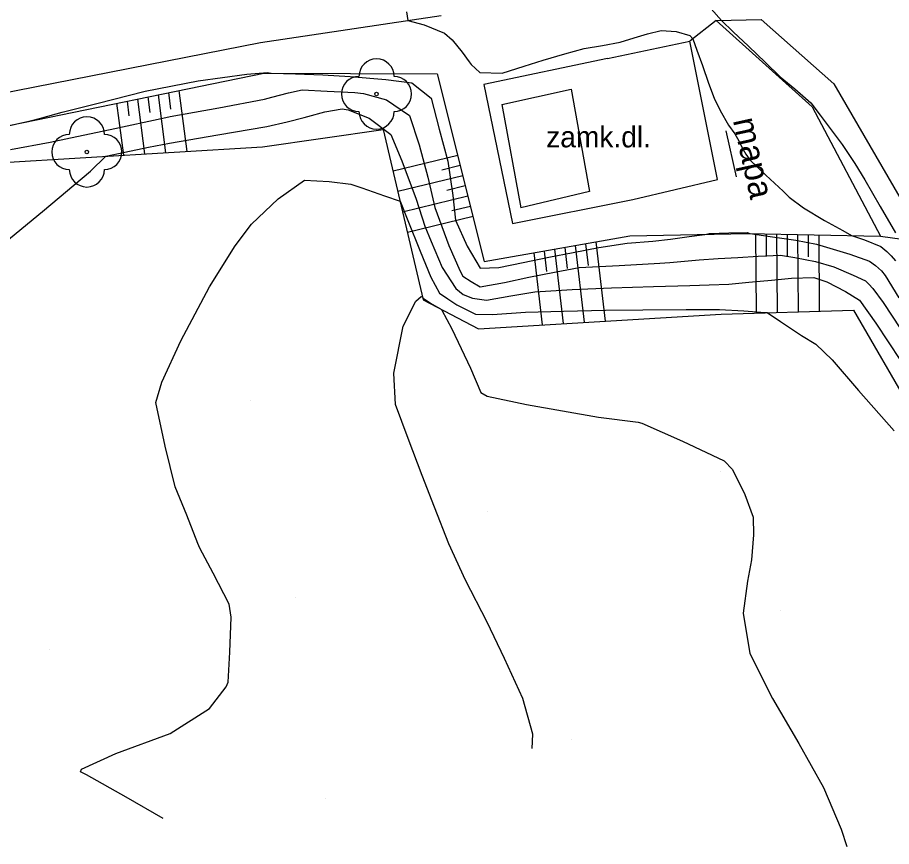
# Model space of a CAD drawing. Extents: x -448957 to -448612, y -1107690 to -1107245.
# Drawn here: x -448777.15 to -448752.23, y -1107406.9 to -1107383.27 of the extents above; entities that cross this region are included whole.
import ezdxf

# ---------------------------------------------------------------- set-up
doc = ezdxf.new("R2010")
doc.units = 0
for name, color, linetype in [('22', 7, 'Continuous'), ('Default', 7, 'Continuous'), ('Vrstva 1', 7, 'Continuous'), ('Vrstva 10', 7, 'Continuous'), ('Vrstva 11', 7, 'Continuous'), ('Vrstva 14', 7, 'Continuous'), ('Vrstva 15', 7, 'Continuous'), ('Vrstva 16', 7, 'Continuous'), ('Vrstva 17', 7, 'Continuous'), ('Vrstva 22', 7, 'Continuous'), ('Vrstva 40', 7, 'Continuous'), ('Vrstva 42', 7, 'Continuous'), ('Vrstva 5', 7, 'Continuous')]:
    doc.layers.add(name, color=color, linetype=linetype)

# ---------------------------------------------------------------- blocks, each defined once
blk = doc.blocks.new('POINT_DISPLAY')
at = {"layer": 'Default'}
blk.add_line((0, 0), (0, 0), dxfattribs=at)
blk = doc.blocks.new('STROM$5')
at = {"layer": '22'}
blk.add_circle((0, 0), 0.5, dxfattribs=at)
for centre, start, end in [((0, 5), 0, 180), ((-5, 0), 90, 270), ((5, 0), 270, 90), ((0, -5), 180, 0)]:
    blk.add_arc(centre, 5, start, end, dxfattribs=at)

msp = doc.modelspace()

# ---------------------------------------------------------------- linework, layer by layer
at = {"layer": 'Vrstva 10'}
for p, q in [((-448770.221, -1107383.984), (-448765.066, -1107383.214)), ((-448778.469, -1107385.6), (-448770.221, -1107383.984)), ((-448760.321, -1107384.439), (-448757.978, -1107383.943)), ((-448757.187, -1107387.892), (-448757.978, -1107383.943)), ((-448760.321, -1107384.439), (-448763.847, -1107385.184)), ((-448763.847, -1107385.184), (-448763.031, -1107389.138)), ((-448759.606, -1107388.461), (-448757.187, -1107387.892)), ((-448763.031, -1107389.138), (-448759.606, -1107388.461))]:
    msp.add_line(p, q, dxfattribs=at)
at = {"layer": 'Vrstva 11'}
for p, q in [((-448757.224, -1107383.358), (-448757.978, -1107383.943)), ((-448757.224, -1107383.358), (-448755.946, -1107383.329)), ((-448755.946, -1107383.329), (-448753.87, -1107385.167)), ((-448753.87, -1107385.167), (-448751.25, -1107389.68))]:
    msp.add_line(p, q, dxfattribs=at)
at = {"layer": 'Vrstva 14'}
for p, q in [((-448757.224, -1107383.358), (-448754.486, -1107385.818)), ((-448778.436, -1107386.561), (-448770.128, -1107384.856)), ((-448770.128, -1107384.856), (-448765.178, -1107384.875)), ((-448765.178, -1107384.875), (-448763.84, -1107390.228)), ((-448754.486, -1107385.818), (-448752.54, -1107389.502)), ((-448770.163, -1107386.956), (-448766.717, -1107386.465)), ((-448766.717, -1107386.465), (-448765.579, -1107391.316)), ((-448778.293, -1107387.451), (-448770.163, -1107386.956)), ((-448763.84, -1107390.228), (-448759.69, -1107389.497)), ((-448759.69, -1107389.497), (-448756.323, -1107389.43)), ((-448756.323, -1107389.43), (-448752.54, -1107389.502)), ((-448752.54, -1107389.502), (-448751.25, -1107389.68)), ((-448765.579, -1107391.316), (-448764.005, -1107392.141)), ((-448757.08, -1107391.723), (-448753.315, -1107391.608)), ((-448753.315, -1107391.608), (-448749.664, -1107397.93)), ((-448764.005, -1107392.141), (-448757.08, -1107391.723))]:
    msp.add_line(p, q, dxfattribs=at)
at = {"layer": 'Vrstva 15'}
for p, q in [((-448772.552, -1107385.353), (-448772.322, -1107387.087)), ((-448773.73, -1107385.595), (-448773.523, -1107387.161)), ((-448773.436, -1107385.535), (-448773.376, -1107385.982)), ((-448773.141, -1107385.474), (-448772.923, -1107387.124)), ((-448772.846, -1107385.414), (-448772.784, -1107385.885)), ((-448774.32, -1107385.716), (-448774.123, -1107387.197)), ((-448774.025, -1107385.656), (-448773.969, -1107386.079)), ((-448764.597, -1107387.2), (-448766.44, -1107387.647)), ((-448764.524, -1107387.491), (-448765.051, -1107387.619)), ((-448764.451, -1107387.782), (-448766.303, -1107388.231)), ((-448764.379, -1107388.073), (-448764.908, -1107388.202)), ((-448764.306, -1107388.364), (-448766.166, -1107388.815)), ((-448764.233, -1107388.656), (-448764.764, -1107388.784)), ((-448764.16, -1107388.947), (-448766.029, -1107389.399)), ((-448756.104, -1107389.434), (-448756.091, -1107391.693)), ((-448755.804, -1107389.44), (-448755.8, -1107390.085)), ((-448755.504, -1107389.446), (-448755.491, -1107391.674)), ((-448755.204, -1107389.451), (-448755.2, -1107390.088)), ((-448754.904, -1107389.457), (-448754.891, -1107391.656)), ((-448754.604, -1107389.463), (-448754.6, -1107390.091)), ((-448754.304, -1107389.468), (-448754.291, -1107391.638)), ((-448761.838, -1107389.875), (-448761.588, -1107391.995)), ((-448761.542, -1107389.823), (-448761.471, -1107390.429)), ((-448761.246, -1107389.771), (-448760.989, -1107391.959)), ((-448760.95, -1107389.719), (-448760.877, -1107390.344)), ((-448760.655, -1107389.667), (-448760.389, -1107391.923)), ((-448762.43, -1107389.98), (-448762.188, -1107392.031)), ((-448762.134, -1107389.928), (-448762.065, -1107390.514))]:
    msp.add_line(p, q, dxfattribs=at)
at = {"layer": 'Vrstva 16'}
msp.add_lwpolyline([(-448777.582, -1107386.398), (-448776.824, -1107386.23), (-448776.455, -1107386.13), (-448775.877, -1107385.97), (-448774.887, -1107385.721), (-448773.504, -1107385.372), (-448771.998, -1107385.077), (-448770.611, -1107384.884), (-448770.024, -1107384.841), (-448769.917, -1107384.857), (-448769.219, -1107384.882), (-448768.445, -1107384.91), (-448767.658, -1107384.952), (-448766.647, -1107385.043), (-448765.903, -1107385.13), (-448765.357, -1107385.569), (-448765.124, -1107386.451), (-448764.882, -1107387.369), (-448764.735, -1107388.34), (-448764.655, -1107389.045), (-448764.328, -1107389.788), (-448763.953, -1107390.416), (-448763.425, -1107390.392), (-448762.731, -1107390.25), (-448761.995, -1107390.101), (-448761.302, -1107389.969), (-448760.574, -1107389.825), (-448759.761, -1107389.707), (-448759.035, -1107389.642), (-448758.526, -1107389.586), (-448757.996, -1107389.517), (-448757.547, -1107389.454), (-448757.503, -1107389.442), (-448757.425, -1107389.424), (-448756.866, -1107389.41), (-448756.334, -1107389.401), (-448756.294, -1107389.416), (-448756.259, -1107389.431), (-448755.685, -1107389.509), (-448754.954, -1107389.616), (-448754.363, -1107389.736), (-448753.413, -1107390.014), (-448752.853, -1107390.22), (-448752.686, -1107390.341), (-448752.516, -1107390.492), (-448752.407, -1107390.621), (-448752.021, -1107391.261)], dxfattribs=at)
at = {"layer": 'Vrstva 17'}
for points in [[(-448766.053, -1107383.114), (-448766.016, -1107383.356), (-448765.554, -1107383.479), (-448764.968, -1107383.715), (-448764.756, -1107383.911), (-448764.473, -1107384.258), (-448764.266, -1107384.539), (-448764.208, -1107384.616), (-448763.962, -1107384.841), (-448763.33, -1107384.858), (-448762.706, -1107384.659), (-448762.162, -1107384.491), (-448761.546, -1107384.305), (-448760.987, -1107384.152), (-448760.47, -1107384.074), (-448759.968, -1107383.974), (-448759.569, -1107383.848), (-448759.187, -1107383.741), (-448758.794, -1107383.647), (-448758.366, -1107383.668), (-448757.98, -1107383.785), (-448757.891, -1107383.876), (-448757.775, -1107384.203), (-448757.621, -1107384.644), (-448757.444, -1107385.14), (-448757.28, -1107385.572), (-448757.116, -1107385.922), (-448756.873, -1107386.337), (-448756.697, -1107386.588), (-448756.583, -1107386.788), (-448756.493, -1107386.967), (-448756.382, -1107387.169), (-448756.268, -1107387.326), (-448755.812, -1107387.766), (-448755.317, -1107388.224), (-448755.142, -1107388.389), (-448754.741, -1107388.697), (-448754.14, -1107389.06), (-448753.616, -1107389.339), (-448753.372, -1107389.486), (-448752.997, -1107389.606), (-448752.534, -1107389.801), (-448752.361, -1107389.944), (-448752.238, -1107390.06), (-448752.111, -1107390.208)], [(-448757.369, -1107383.022), (-448757.076, -1107383.355), (-448756.746, -1107383.677), (-448756.307, -1107384.088), (-448755.818, -1107384.553), (-448755.403, -1107384.964), (-448754.985, -1107385.309), (-448754.53, -1107385.703), (-448754.258, -1107386.055), (-448753.86, -1107386.591), (-448753.63, -1107386.895), (-448753.535, -1107387.034), (-448753.276, -1107387.435), (-448752.991, -1107387.901), (-448752.552, -1107388.661), (-448752.118, -1107389.413)], [(-448777.344, -1107387.032), (-448776.22, -1107386.824), (-448775.637, -1107386.704), (-448774.502, -1107386.461), (-448772.917, -1107386.122), (-448772.792, -1107386.098), (-448771.408, -1107385.842), (-448770.104, -1107385.599), (-448769.9, -1107385.544), (-448769.423, -1107385.416), (-448769.027, -1107385.338), (-448768.322, -1107385.369), (-448767.53, -1107385.406), (-448767.285, -1107385.437), (-448766.631, -1107385.616), (-448765.968, -1107386.061), (-448765.694, -1107386.9), (-448765.446, -1107387.825), (-448765.253, -1107388.684), (-448764.849, -1107389.773), (-448764.53, -1107390.501), (-448764.451, -1107390.645), (-448764.213, -1107390.798), (-448763.952, -1107390.951), (-448763.258, -1107390.826), (-448762.564, -1107390.675), (-448761.837, -1107390.532), (-448761.134, -1107390.396), (-448759.994, -1107390.335), (-448758.83, -1107390.274), (-448758.544, -1107390.251), (-448758.025, -1107390.204), (-448757.712, -1107390.175), (-448757.174, -1107390.144), (-448756.607, -1107390.116), (-448756.025, -1107390.071), (-448755.392, -1107390.041), (-448754.988, -1107390.112), (-448754.394, -1107390.222), (-448753.87, -1107390.378), (-448753.322, -1107390.614), (-448752.969, -1107390.773), (-448752.872, -1107390.869), (-448752.756, -1107390.991), (-448752.466, -1107391.394), (-448751.729, -1107392.509)], [(-448777.681, -1107389.821), (-448776.435, -1107388.801), (-448775.062, -1107387.648), (-448774.632, -1107387.228), (-448774.267, -1107387.15), (-448773.408, -1107386.97), (-448772.811, -1107386.851), (-448771.431, -1107386.613), (-448770.034, -1107386.379), (-448769.459, -1107386.243), (-448768.972, -1107386.12), (-448768.866, -1107386.092), (-448768.388, -1107385.964), (-448767.894, -1107385.871), (-448767.717, -1107385.903), (-448767.116, -1107386.137), (-448766.505, -1107386.607), (-448766.185, -1107387.358), (-448765.782, -1107388.445), (-448765.533, -1107389.217), (-448765.352, -1107389.66), (-448765.04, -1107390.392), (-448764.654, -1107390.999), (-448764.436, -1107391.164), (-448764.171, -1107391.275), (-448763.771, -1107391.329), (-448763.08, -1107391.207), (-448762.396, -1107391.09), (-448761.328, -1107391.021), (-448760.208, -1107390.972), (-448759.011, -1107390.939), (-448757.975, -1107390.913), (-448757.426, -1107390.892), (-448756.862, -1107390.872), (-448756.291, -1107390.818), (-448755.649, -1107390.755), (-448755.076, -1107390.697), (-448754.447, -1107390.685), (-448754.069, -1107390.805), (-448753.536, -1107391.082), (-448753.137, -1107391.332), (-448752.677, -1107391.98), (-448751.975, -1107393.051)], [(-448772.995, -1107406.1), (-448774.052, -1107405.494), (-448775.181, -1107404.851), (-448775.349, -1107404.772), (-448775.321, -1107404.696), (-448774.342, -1107404.246), (-448772.79, -1107403.674), (-448771.669, -1107402.968), (-448771.198, -1107402.343), (-448771.137, -1107402.218), (-448771.098, -1107401.36), (-448771.054, -1107400.364), (-448771.109, -1107399.994), (-448771.564, -1107399.11), (-448771.953, -1107398.394), (-448772.005, -1107398.266), (-448772.318, -1107397.455), (-448772.649, -1107396.645), (-448772.94, -1107395.49), (-448773.205, -1107394.245), (-448773.03, -1107393.664), (-448772.487, -1107392.484), (-448771.674, -1107390.949), (-448770.94, -1107389.779), (-448770.473, -1107389.164), (-448769.718, -1107388.44), (-448768.963, -1107387.906), (-448768.257, -1107387.95), (-448767.647, -1107388.022), (-448767.334, -1107388.129), (-448766.688, -1107388.351), (-448766.238, -1107388.506), (-448766.021, -1107389.054), (-448765.665, -1107389.932), (-448765.366, -1107390.672), (-448765.112, -1107391.132), (-448764.878, -1107391.288), (-448764.619, -1107391.464), (-448764.085, -1107391.724), (-448763.607, -1107391.732), (-448762.668, -1107391.667), (-448761.584, -1107391.641), (-448760.38, -1107391.614), (-448759.316, -1107391.6), (-448758.085, -1107391.595), (-448757.131, -1107391.596), (-448756.436, -1107391.635), (-448755.828, -1107391.677), (-448755.797, -1107391.68), (-448755.771, -1107391.683), (-448755.393, -1107391.936), (-448754.793, -1107392.332), (-448754.387, -1107392.583), (-448753.922, -1107393.025), (-448753.168, -1107393.902), (-448752.149, -1107395.05)], [(-448762.476, -1107404.107), (-448762.455, -1107403.692), (-448762.742, -1107402.677), (-448763.26, -1107401.537), (-448763.757, -1107400.502), (-448764.372, -1107399.312), (-448764.848, -1107398.268), (-448765.254, -1107397.223), (-448765.605, -1107396.329), (-448766.01, -1107395.274), (-448766.369, -1107394.297), (-448766.419, -1107393.41), (-448766.156, -1107392.071), (-448765.786, -1107391.356), (-448765.642, -1107391.224), (-448765.599, -1107391.231), (-448765.584, -1107391.27), (-448765.327, -1107391.442), (-448765.087, -1107391.574), (-448765.07, -1107391.59), (-448765.049, -1107391.614), (-448764.767, -1107392.146), (-448764.231, -1107393.262), (-448763.941, -1107393.96), (-448763.76, -1107394.065), (-448762.63, -1107394.302), (-448760.58, -1107394.665), (-448759.454, -1107394.803), (-448759.342, -1107394.835), (-448758.189, -1107395.344), (-448756.996, -1107395.911), (-448756.76, -1107396.155), (-448756.405, -1107396.865), (-448756.173, -1107397.514), (-448756.158, -1107398.012), (-448756.22, -1107398.725), (-448756.337, -1107399.336), (-448756.46, -1107400.245), (-448756.269, -1107401.401), (-448755.618, -1107402.677), (-448754.867, -1107403.965), (-448754.169, -1107405.212), (-448753.661, -1107406.406), (-448753.497, -1107406.898)]]:
    msp.add_lwpolyline(points, dxfattribs=at)
at = {"layer": 'Vrstva 5'}
for p, q in [((-448763.342, -1107385.752), (-448761.361, -1107385.314)), ((-448761.361, -1107385.314), (-448760.837, -1107388.235)), ((-448763.342, -1107385.752), (-448762.792, -1107388.694)), ((-448756.949, -1107386.5), (-448756.66, -1107387.81)), ((-448760.837, -1107388.235), (-448762.792, -1107388.694))]:
    msp.add_line(p, q, dxfattribs=at)

# ---------------------------------------------------------------- block references
at = {"layer": 'Vrstva 1', "xscale": 0.1, "yscale": 0.10000000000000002}
for p in [(-448757.224, -1107383.358), (-448757.224, -1107383.358), (-448757.224, -1107383.358), (-448755.946, -1107383.329), (-448770.221, -1107383.984), (-448770.221, -1107383.984), (-448757.978, -1107383.943), (-448757.978, -1107383.943), (-448757.978, -1107383.943), (-448760.321, -1107384.439), (-448760.321, -1107384.439), (-448770.128, -1107384.856), (-448765.178, -1107384.875), (-448763.847, -1107385.184), (-448761.361, -1107385.314), (-448753.87, -1107385.167), (-448763.342, -1107385.752), (-448763.342, -1107385.752), (-448754.486, -1107385.818), (-448754.486, -1107385.818), (-448766.717, -1107386.465), (-448756.949, -1107386.5), (-448770.163, -1107386.956), (-448757.187, -1107387.892), (-448756.66, -1107387.81), (-448760.837, -1107388.235), (-448759.606, -1107388.461), (-448762.792, -1107388.694), (-448762.792, -1107388.694), (-448763.031, -1107389.138), (-448759.69, -1107389.497), (-448756.323, -1107389.43), (-448752.54, -1107389.502), (-448752.54, -1107389.502), (-448752.54, -1107389.502), (-448763.84, -1107390.228), (-448765.579, -1107391.316), (-448753.315, -1107391.608), (-448757.08, -1107391.723), (-448764.005, -1107392.141)]:
    msp.add_blockref('POINT_DISPLAY', p, dxfattribs=at)
at = {"layer": 'Vrstva 14', "xscale": 0.1, "yscale": 0.10000000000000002}
for p in [(-448770.505, -1107394.178), (-448757.091, -1107396.216), (-448763.743, -1107397.363), (-448769.229, -1107399.791), (-448755.406, -1107400.179), (-448776.232, -1107401.279), (-448761.347, -1107403.835), (-448768.372, -1107405.529)]:
    msp.add_blockref('POINT_DISPLAY', p, dxfattribs=at)
at = {"layer": 'Vrstva 22', "xscale": 0.1, "yscale": 0.10000000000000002}
for p in [(-448766.911, -1107385.451), (-448775.17, -1107387.103)]:
    msp.add_blockref('STROM$5', p, dxfattribs=at)

# ---------------------------------------------------------------- texts
at = {"layer": 'Vrstva 40'}
msp.add_text('zamk.dl.', height=0.6, dxfattribs=at).set_placement((-448762.074, -1107386.973))
at = {"layer": 'Vrstva 42'}
msp.add_text('mapa', height=0.7, rotation=282.4408, dxfattribs=at).set_placement((-448756.752, -1107386.199))

doc.saveas('drawing.dxf')
